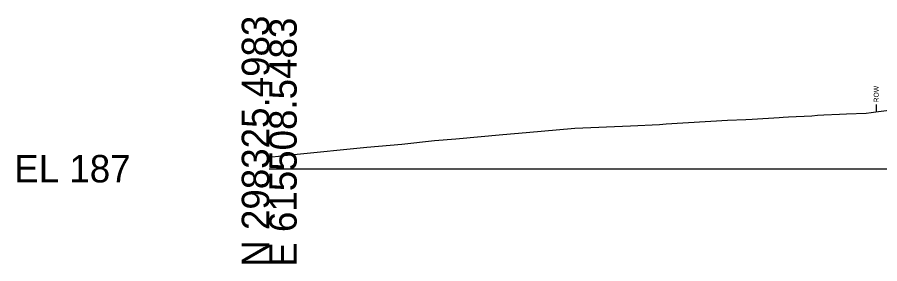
# Model space of a CAD drawing. Extents: x 517327 to 517505, y 114839 to 116885.
# Drawn here: x 517326.7 to 517414.6, y 116338.7 to 116363.8 of the extents above; entities that cross this region are included whole.
import ezdxf

# ---------------------------------------------------------------- set-up
doc = ezdxf.new("R2010")
doc.units = 0
for name, color, linetype in [('Exist XS Ground Line', 7, 'Continuous'), ('Old_Level_63', 7, 'Continuous'), ('Prop XS Exc Vertical Line 2', 7, 'Continuous')]:
    doc.layers.add(name, color=color, linetype=linetype)

msp = doc.modelspace()

# ---------------------------------------------------------------- linework, layer by layer
at = {"layer": 'Exist XS Ground Line'}
for p, q in [((517405.298, 116353.648), (517407.682, 116353.765)), ((517407.682, 116353.765), (517408.277, 116353.807)), ((517408.277, 116353.807), (517408.903, 116353.844)), ((517408.903, 116353.844), (517410.523, 116353.932)), ((517410.523, 116353.932), (517411.217, 116353.958)), ((517411.217, 116353.958), (517413.231, 116354.013)), ((517413.231, 116354.013), (517413.76, 116354.079)), ((517413.76, 116354.079), (517414.235, 116354.149)), ((517414.235, 116354.149), (517416.658, 116354.466)), ((517389.198, 116352.728), (517392.145, 116352.886)), ((517392.145, 116352.886), (517392.856, 116352.943)), ((517392.856, 116352.943), (517399.101, 116353.315)), ((517399.101, 116353.315), (517400.964, 116353.396)), ((517400.964, 116353.396), (517401.596, 116353.428)), ((517401.596, 116353.428), (517404.378, 116353.581)), ((517404.378, 116353.581), (517404.787, 116353.61)), ((517404.787, 116353.61), (517405.298, 116353.648)), ((517376.181, 116351.848), (517378.566, 116352.069)), ((517378.566, 116352.069), (517383.536, 116352.512)), ((517383.536, 116352.512), (517389.198, 116352.728)), ((517365.886, 116350.88), (517369.217, 116351.223)), ((517369.217, 116351.223), (517371.41, 116351.414)), ((517371.41, 116351.414), (517376.181, 116351.848)), ((517354.874, 116349.819), (517362.323, 116350.564)), ((517362.323, 116350.564), (517365.886, 116350.88)), ((517352.365, 116349.543), (517354.874, 116349.819))]:
    msp.add_line(p, q, dxfattribs=at)
at = {"layer": 'Old_Level_63'}
msp.add_line((517352.365, 116348.365), (517427.365, 116348.365), dxfattribs=at)
at = {"layer": 'Prop XS Exc Vertical Line 2'}
msp.add_line((517414.259, 116354.903), (517414.259, 116354.153), dxfattribs=at)

# ---------------------------------------------------------------- texts
at = {"layer": 'Old_Level_63'}
for s, p in [('N 298325.4983', (517352.365, 116338.365)), ('E 615508.5483', (517355.165, 116338.364))]:
    msp.add_text(s, height=2.8, rotation=90, dxfattribs=at).set_placement(p)
msp.add_text('EL 187', height=2.8, dxfattribs=at).set_placement((517326.366, 116346.965))
at = {"layer": 'Prop XS Exc Vertical Line 2'}
msp.add_text('ROW', height=0.5, rotation=90, dxfattribs=at).set_placement((517414.509, 116355.128))

doc.saveas('drawing.dxf')
